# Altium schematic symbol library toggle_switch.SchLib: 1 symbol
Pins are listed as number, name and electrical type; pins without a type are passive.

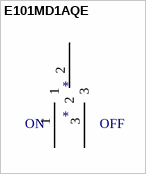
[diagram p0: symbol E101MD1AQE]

## E101MD1AQE
designator *
C&K SWITCH TOGGLE SPDT 7.5A 125V
footprint E101MD1AQE (Footprint not found)
pins: 1, 2, 3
